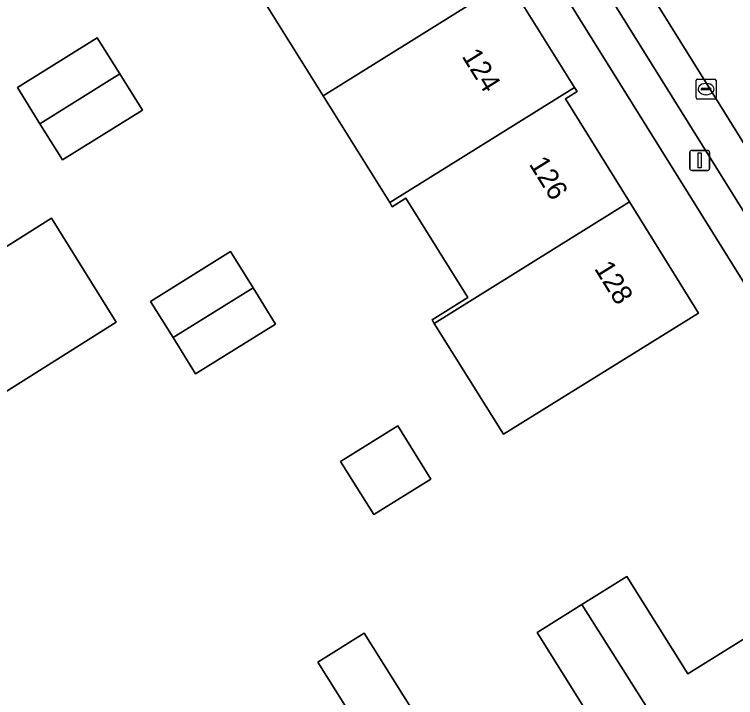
# Model space of a CAD drawing. Extents: x 159352 to 160617, y 385888 to 387323.
# Drawn here: x 159675.99 to 159712.05, y 385936.83 to 385970.99 of the extents above; entities that cross this region are included whole.
import ezdxf

# ---------------------------------------------------------------- set-up
doc = ezdxf.new("R2010")
doc.units = 0
for name, color, linetype in [('IMGEO_Erf', 7, 'Continuous'), ('IMGEO_Kolk', 7, 'Continuous'), ('IMGEO_Lichtmast', 7, 'Continuous'), ('IMGEO_Pand', 7, 'Continuous'), ('IMGEO_Pand_nummerreeks', 7, 'Continuous'), ('IMGEO_Parkeervlak_open', 7, 'Continuous'), ('IMGEO_Rijbaan_lokaal_open', 7, 'Continuous'), ('IMGEO_Voetpad_open', 7, 'Continuous')]:
    doc.layers.add(name, color=color, linetype=linetype)

msp = doc.modelspace()

# ---------------------------------------------------------------- linework, layer by layer
at = {"layer": 'IMGEO_Erf'}
for points in [[(159726.677, 385934.766), (159683.777, 386003.638), (159684.463, 386004.075), (159676.127, 386017.48), (159664.396, 386036.344)], [(159700.666, 385972.682), (159703.999, 385967.336), (159704.125, 385967.134), (159703.549, 385966.769), (159706.743, 385961.623), (159710.197, 385956.058), (159700.437, 385949.995), (159696.983, 385955.539), (159696.873, 385955.715), (159698.661, 385956.829), (159695.565, 385961.797), (159694.886, 385961.374), (159694.759, 385961.577), (159691.427, 385966.923), (159688.093, 385972.273)], [(159705.168, 385935.207), (159702.121, 385940.084), (159704.365, 385941.486), (159706.607, 385942.887), (159709.654, 385938.011), (159712.662, 385939.89), (159715.667, 385941.768), (159712.62, 385946.644), (159715.147, 385948.223), (159721.911, 385937.512), (159719.777, 385936.172)], [(159693.573, 385934.742), (159691.163, 385938.6), (159693.484, 385940.049), (159695.894, 385936.192)]]:
    msp.add_lwpolyline(points, dxfattribs=at)
for points in [[(159680.135, 385969.825), (159681.264, 385968.016), (159682.392, 385966.207), (159678.396, 385963.714), (159677.268, 385965.523), (159676.139, 385967.332)], [(159677.848, 385960.799), (159681.084, 385955.605), (159673.355, 385950.733), (159670.092, 385955.91)], [(159686.8, 385959.128), (159687.925, 385957.317), (159689.05, 385955.505), (159685.054, 385953.025), (159683.928, 385954.831), (159682.802, 385956.637)], [(159695.153, 385950.416), (159696.811, 385947.749), (159693.961, 385945.976), (159692.3, 385948.636)]]:
    msp.add_lwpolyline(points, close=True, dxfattribs=at)
at = {"layer": 'IMGEO_Kolk'}
for p, q in [((159710.071, 385966.826), (159710.071, 385967.678)), ((159710.146, 385967.752), (159710.998, 385967.752)), ((159711.072, 385967.678), (159711.072, 385966.826)), ((159710.559, 385967.532), (159710.584, 385967.532)), ((159710.33, 385967.246), (159710.33, 385967.258)), ((159710.768, 385967.209), (159710.37, 385967.209)), ((159710.373, 385967.295), (159710.771, 385967.295)), ((159710.582, 385966.972), (159710.557, 385966.972)), ((159710.814, 385967.258), (159710.814, 385967.246)), ((159710.998, 385966.752), (159710.146, 385966.752))]:
    msp.add_line(p, q, dxfattribs=at)
for points in [[(159710.071, 385966.826), (159710.071, 385967.678)], [(159710.146, 385967.752), (159710.998, 385967.752)], [(159711.072, 385967.678), (159711.072, 385966.826)], [(159710.998, 385966.752), (159710.146, 385966.752)]]:
    msp.add_lwpolyline(points, dxfattribs=at)
for centre, radius, start, end in [((159710.148, 385967.676), 0.0765, 91.552, 178.448), ((159710.148, 385967.676), 0.0765, 91.552, 178.448), ((159710.996, 385967.676), 0.0765, 1.552, 88.448), ((159710.996, 385967.676), 0.0765, 1.552, 88.448), ((159710.37, 385967.255), 0.0403, 85.8775, 175.7526), ((159710.367, 385967.245), 0.0366, 178.938, 274.7102), ((159710.771, 385967.252), 0.043, 264.8664, 352.4533), ((159710.775, 385967.257), 0.0386, 1.7309, 96.639), ((159710.148, 385966.828), 0.0765, 181.552, 268.448), ((159710.148, 385966.828), 0.0765, 181.552, 268.448), ((159710.996, 385966.828), 0.0765, 271.552, 358.448), ((159710.996, 385966.828), 0.0765, 271.552, 358.448)]:
    msp.add_arc(centre, radius, start, end, dxfattribs=at)
for centre, major_axis, ratio, start_param, end_param in [((159710.558, 385967.252), (-0.387, 0.002), 0.722429, 4.712389, 7.853982), ((159710.583, 385967.252), (-0.39, 0.002), 0.717154, 1.570796, 4.712389)]:
    msp.add_ellipse(centre, major_axis=major_axis, ratio=ratio, start_param=start_param, end_param=end_param, dxfattribs=at)
at = {"layer": 'IMGEO_Lichtmast'}
for p, q in [((159709.756, 385963.29), (159709.756, 385964.09)), ((159709.756, 385964.09), (159709.756, 385963.29)), ((159709.856, 385964.19), (159710.646, 385964.19)), ((159710.646, 385964.19), (159709.856, 385964.19)), ((159710.746, 385964.09), (159710.746, 385963.29)), ((159710.746, 385963.29), (159710.746, 385964.09)), ((159710.646, 385963.19), (159709.856, 385963.19)), ((159709.856, 385963.19), (159710.646, 385963.19))]:
    msp.add_line(p, q, dxfattribs=at)
msp.add_lwpolyline([(159710.176, 385964.065), (159710.326, 385964.065), (159710.326, 385963.315), (159710.176, 385963.315), (159710.176, 385964.065)], dxfattribs=at)
for centre, start, end in [((159709.856, 385964.09), 90, 180), ((159709.856, 385964.09), 90, 180), ((159710.646, 385964.09), 0, 90), ((159710.646, 385964.09), 360, 90), ((159709.856, 385963.29), 180, 270), ((159709.856, 385963.29), 180, 270), ((159710.646, 385963.29), 270, 0), ((159710.646, 385963.29), 270, 0)]:
    msp.add_arc(centre, 0.1, start, end, dxfattribs=at)
at = {"layer": 'IMGEO_Pand'}
for points in [[(159688.093, 385972.273), (159691.427, 385966.923), (159700.666, 385972.682), (159700.565, 385972.856), (159699.391, 385972.121), (159696.161, 385977.302)], [(159703.999, 385967.336), (159700.666, 385972.682), (159691.427, 385966.923), (159694.759, 385961.577)], [(159681.264, 385968.016), (159680.135, 385969.825), (159676.139, 385967.332), (159677.268, 385965.523)], [(159677.268, 385965.523), (159678.396, 385963.714), (159682.392, 385966.207), (159681.264, 385968.016)], [(159694.759, 385961.577), (159694.886, 385961.374), (159695.565, 385961.797), (159698.661, 385956.829), (159696.873, 385955.715), (159696.983, 385955.539), (159706.743, 385961.623), (159703.549, 385966.769), (159704.125, 385967.134), (159703.999, 385967.336)], [(159696.983, 385955.539), (159700.437, 385949.995), (159710.197, 385956.058), (159706.743, 385961.623)], [(159681.084, 385955.605), (159677.848, 385960.799), (159670.092, 385955.91), (159673.355, 385950.733)], [(159687.925, 385957.317), (159686.8, 385959.128), (159682.802, 385956.637), (159683.928, 385954.831)], [(159683.928, 385954.831), (159685.054, 385953.025), (159689.05, 385955.505), (159687.925, 385957.317)], [(159696.811, 385947.749), (159695.153, 385950.416), (159692.3, 385948.636), (159693.961, 385945.976)], [(159711.471, 385930.233), (159716.466, 385933.356), (159716.933, 385932.61), (159717.167, 385932.756), (159712.662, 385939.89), (159709.654, 385938.011), (159706.607, 385942.887), (159704.365, 385941.486)], [(159706.158, 385926.91), (159711.471, 385930.233), (159704.365, 385941.486), (159702.121, 385940.084), (159705.168, 385935.207), (159702.121, 385933.303)], [(159693.573, 385934.742), (159695.894, 385936.192), (159693.484, 385940.049), (159691.163, 385938.6)]]:
    msp.add_lwpolyline(points, close=True, dxfattribs=at)
at = {"layer": 'IMGEO_Parkeervlak_open'}
for points in [[(159729.51, 385937.17), (159689.128, 386002.021)], [(159689.162, 385998.525), (159714.229, 385958.291)]]:
    msp.add_lwpolyline(points, dxfattribs=at)
at = {"layer": 'IMGEO_Rijbaan_lokaal_open'}
msp.add_lwpolyline([(159729.606, 385937.026), (159733.392, 385939.433), (159733.253, 385939.657), (159690.064, 386009.27), (159688.08, 386012.469), (159676.243, 386030.847), (159672.6, 386028.467), (159676.012, 386023.063), (159685.883, 386007.217), (159686.951, 386005.519), (159689.128, 386002.021), (159729.51, 385937.17)], close=True, dxfattribs=at)
at = {"layer": 'IMGEO_Voetpad_open'}
for points in [[(159669.792, 386033.391), (159665.503, 386040.276), (159667.526, 386041.555), (159666.211, 386043.692), (159665.019, 386042.984), (159664.447, 386037.85), (159664.396, 386036.344), (159676.127, 386017.48), (159684.463, 386004.075), (159683.777, 386003.638), (159726.677, 385934.766), (159729.867, 385936.632), (159729.606, 385937.026), (159729.51, 385937.17)], [(159726.497, 385938.638), (159716.071, 385955.325), (159715.692, 385955.092), (159713.835, 385958.065), (159714.229, 385958.291), (159689.162, 385998.525)]]:
    msp.add_lwpolyline(points, dxfattribs=at)

# ---------------------------------------------------------------- texts
at = {"layer": 'IMGEO_Pand_nummerreeks'}
for s, rotation, p in [('124', 301.9223, (159698.332, 385968.9)), ('126', 301.9223, (159701.693, 385963.506)), ('128', 301.8288, (159704.955, 385958.284))]:
    msp.add_text(s, height=1, rotation=rotation, dxfattribs=at).set_placement(p)

doc.saveas('drawing.dxf')
